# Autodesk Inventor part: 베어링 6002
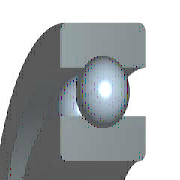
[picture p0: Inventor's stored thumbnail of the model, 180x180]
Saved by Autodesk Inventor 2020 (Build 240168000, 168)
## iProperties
Created: 2012-02
Part Number: 베어링 6002
Material: 강철, 연강
Description: 깊은 그루브 볼 베어링
Document SubType Name: Modeling
Standard: KS B 2023
Designer: mduedu
Standards Organization: KS
Language: ko-KR
Size Designation: 6002 - 15 x 32 x 9
Categories: <MemberInstance><Categories><Category DisplayName="샤프트 부품" InternalName="7f7aeb1f-a693-4053-b835-cee3144e0d98" Mnemonic="SHFT"><Category DisplayName="베어링" Inter
Density: 1 g/cm^3
Appearance: 노란색
IsCustomPart: 0
Author: mduedu
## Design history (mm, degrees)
sketch "스케치" dims "d0" = 4.42 (= -0.26 x WD + 0.26 x BD)
  geometry: L1 (2.29, 11.75)-(6.71, 11.75); L2 (4.5, 11.75)-(4.5, 9.54); L3 (4.5, 11.75)-(4.5, 13.96); L4 (2.858, 10.271)-(0, 10.271); L5 (0, 7.5)-(9, 7.5); L6 (2.858, 13.229)-(0, 13.229); L7 (0, 16)-(9, 16); L8 (9, 7.5)-(9, 10.271); L9 (6.142, 10.271)-(9, 10.271); L10 (6.142, 13.229)-(9, 13.229); L11 (9, 16)-(9, 13.229); L12 (-1.4, 0)-(8.4, 0) reference; L13 (0, -0.3)-(0, 5.3) reference
  constraints: 22 end point, 4 point on line, 2 collinear, 2 perpendicular, 2 symmetric about line, 1 midpoint, 1 parallel, 14 other
  dimensions: "d9" = 15 diameter of L5 L12 (= WD); "d11" = 32 diameter of L7 L12 (= BD); "d12" = 9 distance between parallel lines of L8 L13 (= KB); "d13" = 20.542 diameter of L9 L12 (= 0.326 x BD + 0.674 x WD)
revolve "본체" stored, may be unused: angle "d6" = 90 deg
revolve "볼" stored, may be unused: angle "d7" = 90 deg
pattern_circular "IDS_ARRAYBALL[SIMPL:T]" dims angle "d3" = 360 deg
body "Solid1"
fillet "모깎기1" dims "d1" = 0.3 (= KRS)
other parameters: "WD" = 15 [user parameter; used in 5 equation terms], "BD" = 32 [user parameter; used in 5 equation terms], "KB" = 9 [user parameter; used in 1 equation term], "KRS" = 0.3 [user parameter; used in 1 equation term], "d4" = 0, "d5" = 0, "d8" = 0, "d14" = 0, "d15" = 0, "BBA" = 0 [user parameter], "BC0" = 2850000 [user parameter], "BC" = 5590000 [user parameter], "BR" = 16 (= 0.5 x BD) [user parameter], "WR" = 7.5 (= 0.5 x WD) [user parameter]
